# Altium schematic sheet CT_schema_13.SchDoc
size 391 x 278 mm
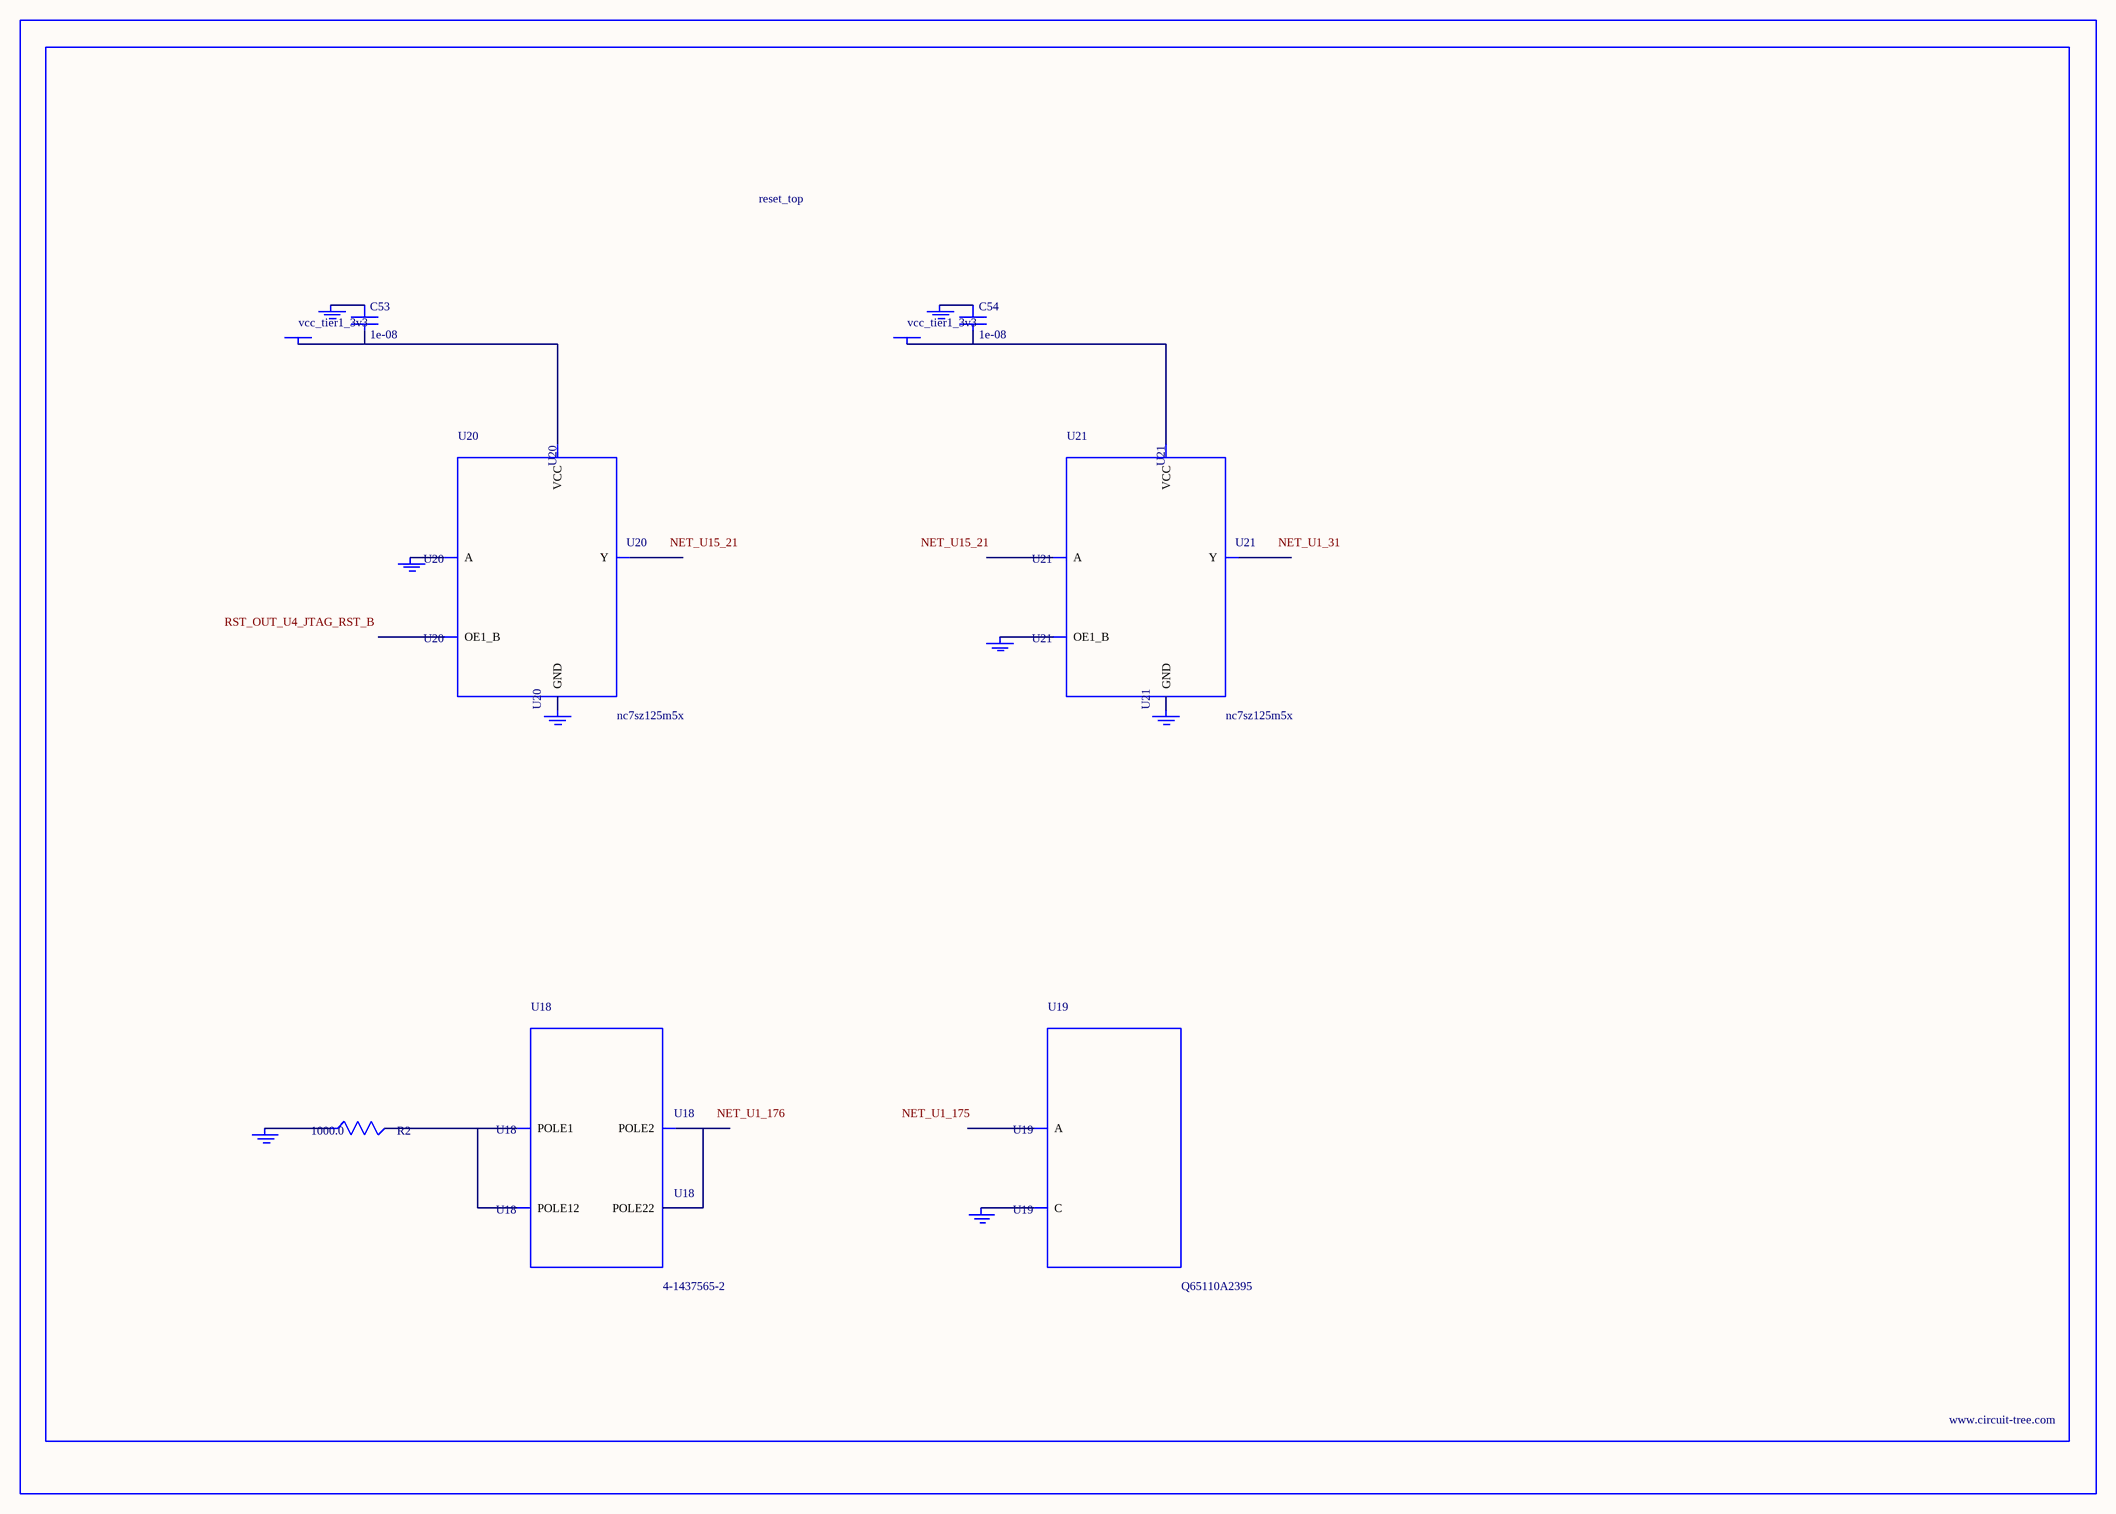
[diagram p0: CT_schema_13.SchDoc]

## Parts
BORDER12  (no value)
C53  1e-08  [C0402]
C54  1e-08  [C0402]
GND_INSTANCE_12_0  (no value)
GND_INSTANCE_12_1  (no value)
GND_INSTANCE_12_2  (no value)
GND_INSTANCE_12_3  (no value)
GND_INSTANCE_12_4  (no value)
GND_INSTANCE_12_5  (no value)
GND_INSTANCE_12_6  (no value)
GND_INSTANCE_12_7  (no value)
POWER_INSTANCE_12_0  vcc_tier1_3v3
POWER_INSTANCE_12_1  vcc_tier1_3v3
R2  1000.0  [R0603]
U18  4-1437565-2  [SW_4-1437565-2]
U19  Q65110A2395  [LGM67K-G1J2-24-Z]
U20  nc7sz125m5x  [NC7SZ125M5X]
U21  nc7sz125m5x  [NC7SZ125M5X]

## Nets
NetC53_1: C53.1 GND_INSTANCE_12_2.0(GND)
NetC53_2: C53.2 POWER_INSTANCE_12_0.0(PWR) U20.5(VCC)
NetC54_1: C54.1 GND_INSTANCE_12_5.0(GND)
NetC54_2: C54.2 POWER_INSTANCE_12_1.0(PWR) U21.5(VCC)
NetGND_INSTANCE_12_0_0: GND_INSTANCE_12_0.0(GND) R2.1
NetGND_INSTANCE_12_1_0: GND_INSTANCE_12_1.0(GND) U19.C
NetGND_INSTANCE_12_3_0: GND_INSTANCE_12_3.0(GND) U20.2(A)
NetGND_INSTANCE_12_4_0: GND_INSTANCE_12_4.0(GND) U20.3(GND)
NetGND_INSTANCE_12_6_0: GND_INSTANCE_12_6.0(GND) U21.1(OE1_B)
NetGND_INSTANCE_12_7_0: GND_INSTANCE_12_7.0(GND) U21.3(GND)
NetR2_2: R2.2 U18.1(POLE1) U18.2(POLE12)
NetU18_3: U18.3(POLE2) U18.4(POLE22)

Not connected (* = marked no-connect by the designer): U19 A; U20 1(OE1_B) 4(Y); U21 2(A) 4(Y)

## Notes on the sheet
- Labels drawn without touching a wire or pin: NET_U1_31, NET_U1_175, NET_U1_176, NET_U15_21, RST_OUT_U4_JTAG_RST_B

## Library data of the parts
BORDER12 = BORDER_PAGE12
C53 C54 = C0402C103K3RAC
GND_INSTANCE_12_0-GND_INSTANCE_12_7 = GND
POWER_INSTANCE_12_0 POWER_INSTANCE_12_1 = PWR
R2 = RC0603JR-071KL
